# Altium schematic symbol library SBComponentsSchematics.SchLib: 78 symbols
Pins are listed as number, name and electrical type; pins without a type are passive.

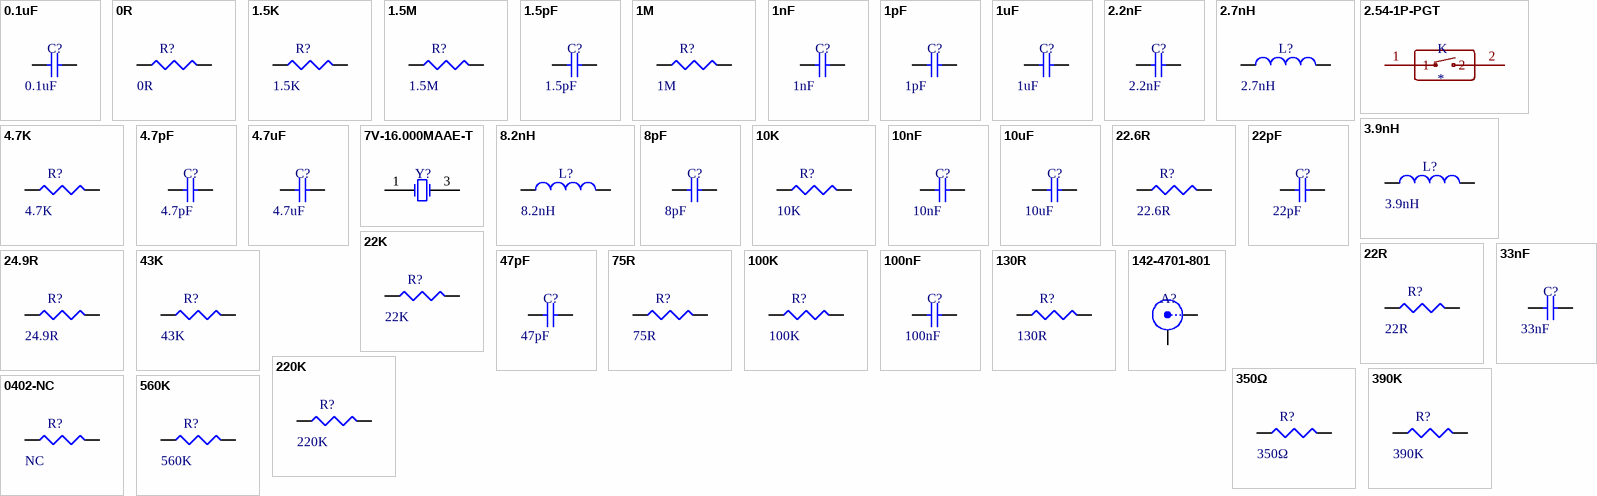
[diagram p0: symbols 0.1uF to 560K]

## 0.1uF
designator C?
footprint 0603 (Chip Body 1.6 x 0.8 mm (LxW typ))
pins: 1, 2

## 0R
designator R?
0R 0402 1/16W ±0.05R
footprint 0402 (Chip Body 1.0 x 0.5 mm (LxW typ))
footprint 0603 (Chip Body 1.6 x 0.8 mm (LxW typ))
pins: 1, 2

## 1.5K
designator R?
1.5K 0402 1/16W ±1%
footprint 0402 (Chip Body 1.0 x 0.5 mm (LxW typ))
pins: 1, 2

## 1.5M
designator R?
1.5M 0402 1/16W ±1%
footprint 0402 (Chip Body 1.0 x 0.5 mm (LxW typ))
pins: 1, 2

## 1.5pF
designator C?
1.5pF 0402 NP0/CG0 50V ±0.1pF
footprint 0402 (Chip Body 1.0 x 0.5 mm (LxW typ))
pins: 1, 2

## 1M
designator R?
1M 0402 1/16W ±1%
footprint 0402 (Chip Body 1.0 x 0.5 mm (LxW typ))
pins: 1, 2

## 1nF
designator C?
1nF 0402 NP0 50V ±5%
footprint 0402 (Chip Body 1.0 x 0.5 mm (LxW typ))
pins: 1, 2

## 1pF
designator C?
1pF 0402 NP0/CG0 50V ±0.1pF
footprint 0402 (Chip Body 1.0 x 0.5 mm (LxW typ))
pins: 1, 2

## 1uF
designator C?
1uF 0603 X5R 10V ±10%
footprint 0603 (Chip Body 1.6 x 0.8 mm (LxW typ))
pins: 1, 2

## 2.2nF
designator C?
2.2nF 0402 X7R 50V ±10%
footprint 0402 (Chip Body 1.0 x 0.5 mm (LxW typ))
pins: 1, 2

## 2.7nH
designator L?
2.7nH ±0.1nH 0402
footprint 0402 (Chip Body 1.0 x 0.5 mm (LxW typ))
pins: 1, 2

## 2.54-1P-PGT
designator K
pins: 1, 2

## 3.9nH
designator L?
3.9nH ±0.1nH 0402
footprint 0402 (Chip Body 1.0 x 0.5 mm (LxW typ))
pins: 1, 2

## 4.7K
designator R?
footprint 0402 (Chip Body 1.0 x 0.5 mm (LxW typ))
footprint 0603 (Chip Body 1.6 x 0.8 mm (LxW typ))
pins: 1, 2

## 4.7pF
designator C?
4.7pF 0402 NP0/CG0 50V ±0.25pF
footprint 0402 (Chip Body 1.0 x 0.5 mm (LxW typ))
pins: 1, 2

## 4.7uF
designator C?
4.7uF 0603 X5R 10V ±10%
footprint 0603 (Chip Body 1.6 x 0.8 mm (LxW typ))
pins: 1, 2

## 7V-16.000MAAE-T
designator Y?
TXC - 7V-16.000MAAE-T, 16MHZ, 30PPM, 12PF - CRYSTAL
footprint 3.2x2.5 CRYSTAL
pins: 1 X1, 2 GND hidden to GND, 3 X2, 4 GND hidden to GND

## 8.2nH
designator L?
8.2nH ±0.2nH 0402
footprint 0402 (Chip Body 1.0 x 0.5 mm (LxW typ))
pins: 1, 2

## 8pF
designator C?
8pF 0402 C0G/NP0 50V ±0.5pF
footprint 0402 (Chip Body 1.0 x 0.5 mm (LxW typ))
pins: 1, 2

## 10K
designator R?
10K 0402 1/16W ±1%
footprint 0402 (Chip Body 1.0 x 0.5 mm (LxW typ))
pins: 1, 2

## 10nF
designator C?
10nF 0402 X7R 25V ±5%
footprint 0402 (Chip Body 1.0 x 0.5 mm (LxW typ))
pins: 1, 2

## 10uF
designator C?
10uF 0603 X5R 6.3V ±20%
footprint 0603 (Chip Body 1.6 x 0.8 mm (LxW typ))
pins: 1, 2

## 22.6R
designator R?
22.6R 0402 1/16W ±0.05R
footprint 0402 (Chip Body 1.0 x 0.5 mm (LxW typ))
pins: 1, 2

## 22K
designator R?, comment value 22K  (hidden comment: 22K 0402 1/16W ±1%)
footprint 0402 (Chip Body 1.0 x 0.5 mm (LxW typ))
pins: 1, 2

## 22pF
designator C?
22pF 0402 NP0/CG0 50V ±5%
footprint 0402 (Chip Body 1.0 x 0.5 mm (LxW typ))
pins: 1, 2

## 22R
designator R?
22R 0402 1/16W ±1%
footprint 0402 (Chip Body 1.0 x 0.5 mm (LxW typ))
pins: 1, 2

## 24.9R
designator R?
24.9R 0402 1/16W ±0.05R
footprint 0402 (Chip Body 1.0 x 0.5 mm (LxW typ))
pins: 1, 2

## 33nF
designator C?
33nF 0402 X7R 50V ±10%
footprint 0402 (Chip Body 1.0 x 0.5 mm (LxW typ))
pins: 1, 2

## 43K
designator R?
43K 0402 1/16W ±1%
footprint 0402 (Chip Body 1.0 x 0.5 mm (LxW typ))
pins: 1, 2

## 47pF
designator C?
47pF 0402 NP0 50V ±5%
footprint 0402 (Chip Body 1.0 x 0.5 mm (LxW typ))
pins: 1, 2

## 75R
designator R?
75R 0402 1/16W ±1%
footprint 0402 (Chip Body 1.0 x 0.5 mm (LxW typ))
pins: 1, 2

## 100K
designator R?
100K 0402 1/16W ±1%
footprint 0402 (Chip Body 1.0 x 0.5 mm (LxW typ))
pins: 1, 2

## 100nF
designator C?
100nF 0402 X7R 16V ±10%
footprint 0402 (Chip Body 1.0 x 0.5 mm (LxW typ))
pins: 1, 2

## 130R
designator R?
130R 0402 1/16W ±0.05R
footprint 0402 (Chip Body 1.0 x 0.5 mm (LxW typ))
pins: 1, 2

## 142-4701-801
designator A?  (value not drawn)
JOHNSON  142-4701-801  SMA FEMELLE REVERSE POLARITY TERMINAISON
footprint 142-4701-801
pins: 1 X, 2 Y

## 220K
designator R?  value 220K
220K 0402 1/16W ±1%
footprint 0402 (Chip Body 1.0 x 0.5 mm (LxW typ))
pins: 1, 2

## 350Ω
designator R?
footprint 0402 (Chip Body 1.0 x 0.5 mm (LxW typ))
footprint 0603 (Chip Body 1.6 x 0.8 mm (LxW typ))
pins: 1, 2

## 390K
designator R?  value 390K
390K 0402 1/16W ±1%
footprint 0402 (Chip Body 1.0 x 0.5 mm (LxW typ))
pins: 1, 2

## 0402-NC
designator R?  value NC  (hidden comment: 0402-NC)
NOT CONNECTED
footprint 0402 - NOBODY (Chip Body 1.0 x 0.5 mm (LxW typ))
pins: 1, 2

## 560K
designator R?
560K 0402 1/16W ±1%
footprint 0402 (Chip Body 1.0 x 0.5 mm (LxW typ))
pins: 1, 2

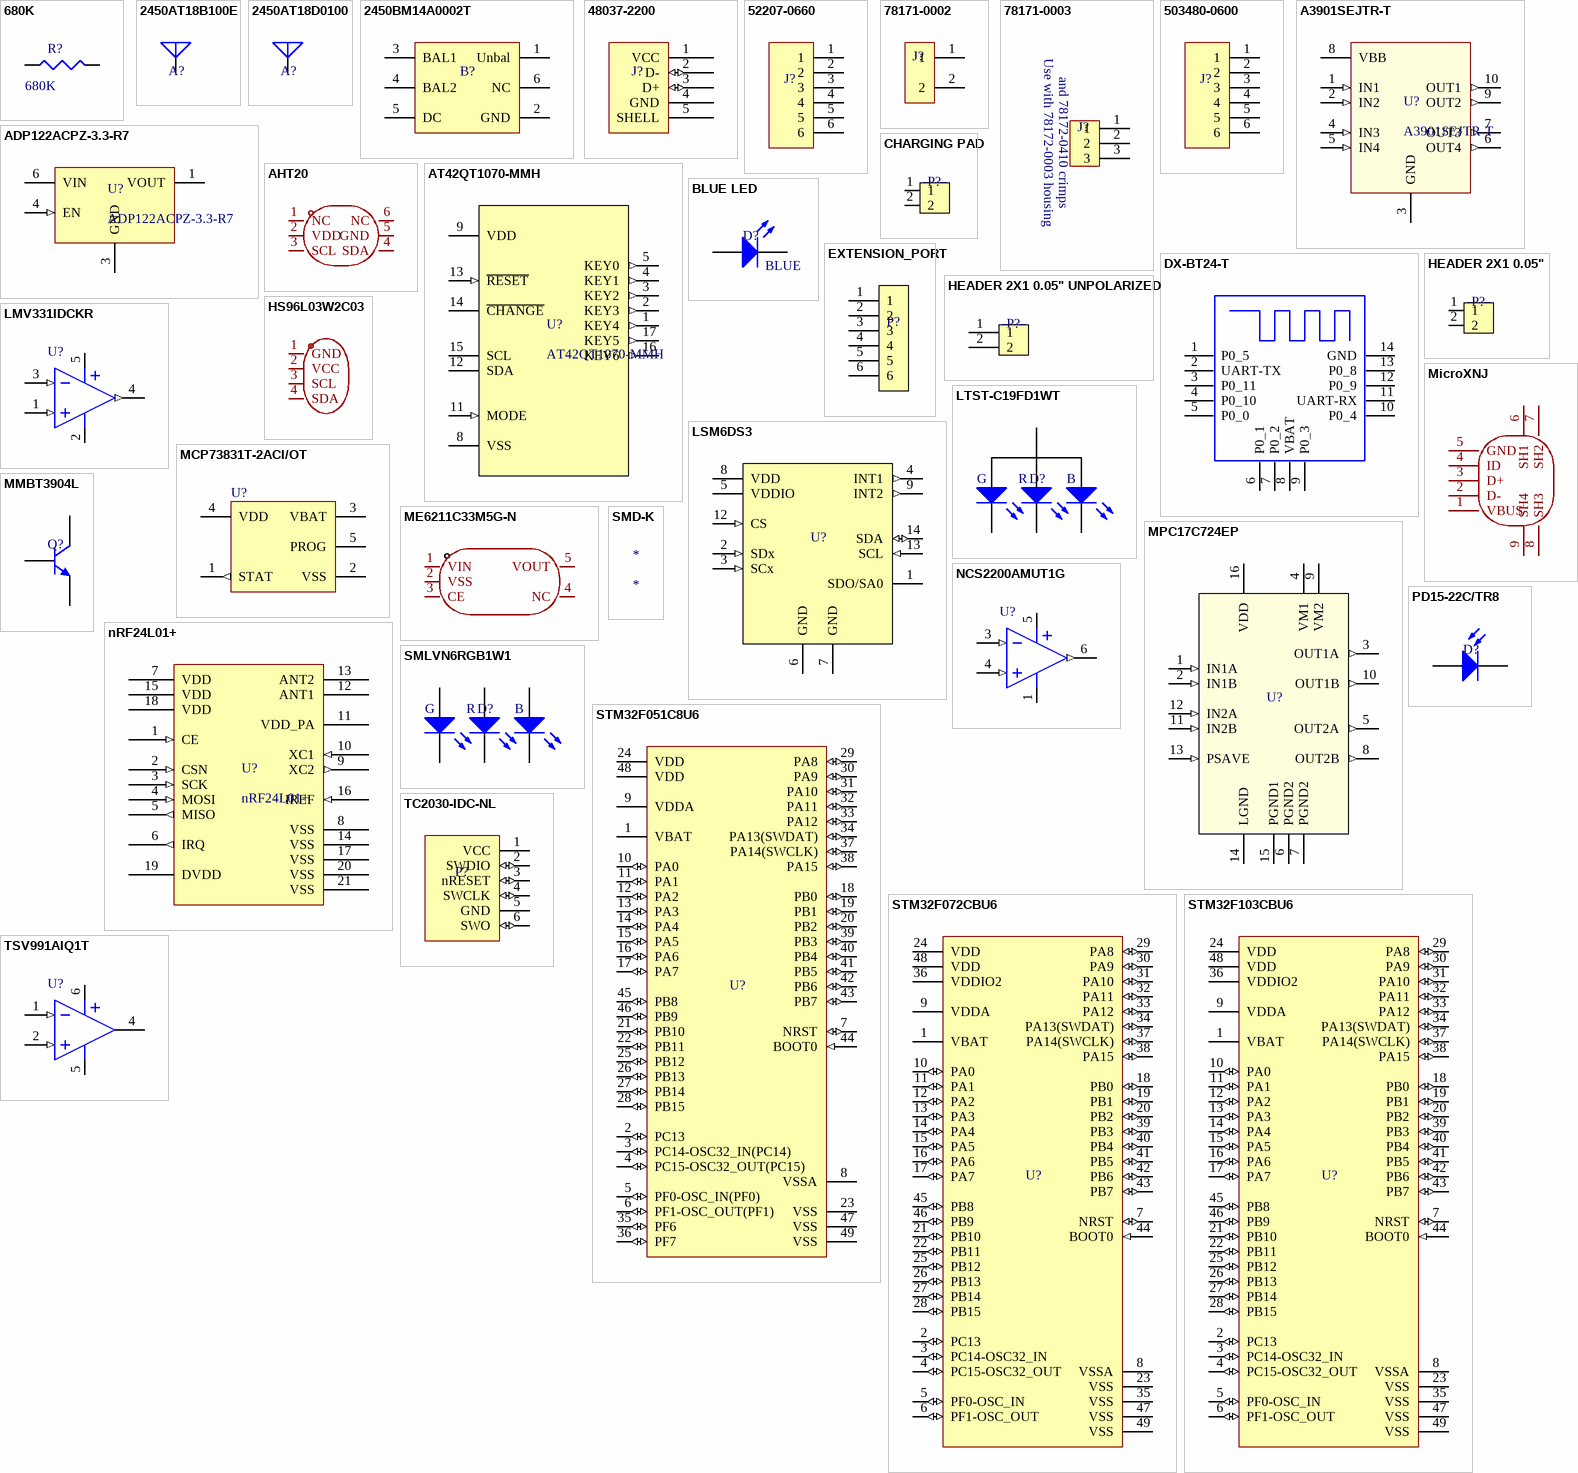
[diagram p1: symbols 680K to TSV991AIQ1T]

## 680K
designator R?  value 680K
680K 0402 1/16W ±1%
footprint 0402 (Chip Body 1.0 x 0.5 mm (LxW typ))
pins: 1, 2

## 2450AT18B100E
designator A?  (value not drawn)
JOHANSON TECHNOLOGY 2450AT18B100E  ANTENNA, CERAMIC, 2.45GHZ
footprint 2450AT18B100E (ANTENNA CHIP 2.4GHZ)
pins: 1 A

## 2450AT18D0100
designator A?  (value not drawn)
JOHANSON TECHNOLOGY 2450AT18D0100  ANTENNA, CERAMIC, 2.45GHZ
footprint 2450AT18D0100 (ANTENNA CHIP 2.4GHZ)
pins: 1 A, 2 GND hidden to GND

## 2450BM14A0002T
designator B?  (value not drawn)
Johanson Technology Impedance Matched Balun Filter Integrated Passive for nRF24L01
footprint 2450BM14A0002 (2.45 GHz Impedance Matched Balun-Filter: Optimized for Nordic's Chipset nRF24L01)
pins: 1 Unbal, 2 GND, 3 BAL1, 4 BAL2, 5 DC, 6 NC

## 48037-2200
designator J?  (value not drawn)
Molex USB 2.0 Connector Plug USB Type A
footprint 48037-2200 (Molex 48037-2200 USB Type A Receptacle)
pins: 1 VCC (power), 2 D- (io), 3 D+ (io), 4 GND (power), 5 SHELL (power)

## 52207-0660
designator J?  (value not drawn)
Easy-On™ Type FFC/FPC Connector, Right-Angle, Surface Mount, ZIF, Top Contact Style Receptacle, 6 Circuits, Gold (Au) Contact Plating, High Barrier Packaging
pins: 1, 2, 3, 4, 5, 6

## 78171-0002
designator J?  (value not drawn)
Molex Pico-EZmate™ Wire-to-Board Header, 2 contacts
footprint 78171-0002
pins: 1, 2

## 78171-0003
designator J?  (value not drawn)
Molex Pico-EZmate™ Wire-to-Board Header, 3 contacts
footprint 78171-0003
pins: 1, 2, 3

## 503480-0600
designator J?  (value not drawn)
Molex 0.50mm Pitch Easy-On™ BackFlip™ Type FPC Connector, 6 contacts
footprint 503480-0600
pins: 1, 2, 3, 4, 5, 6

## A3901SEJTR-T
designator U?
ALLEGRO MICROSYSTEMS - A3901SEJTR-T - IC, MOTOR DRIVER
footprint DFN50P300X300X75_HS-11N
pins: 1 IN1 (in), 2 IN2 (in), 3 GND (power), 4 IN3 (in), 5 IN4 (in), 6 OUT4 (out), 7 OUT3 (out), 8 VBB (power), 9 OUT2 (out), 10 OUT1 (out), 11 PAD (power) hidden to GND

## ADP122ACPZ-3.3-R7
designator U?
Analog Devices ADP122ACPZ-3.3-R7 - 5.5 V Input, 300 mA, Low Quiescent  Current, CMOS Linear Regulator
footprint LFCSP-6 2.0X2.0X0.55 (. 6-Lead Lead Frame Chip Scale Package [LFCSP_UD]  2.00 mm× 2.00 mm Body, Ultra Thin, Dual Lead  (CP-6-3))
pins: 1 VOUT (power) "Regulated Output Voltage.", 2 NC hidden to GND "No Connect. These pins are not internally bonded. They can be left floating or connected  to ground.", 3 GND (power) "Ground", 4 EN (in) "N Enable Input. Drive EN high to turn on the regulator; drive EN low to turn off the  regulator. For automatic startup, connect EN to VIN.", 5 NC hidden to GND "No Connect. These pins are not internally bonded. They can be left floating or connected  to ground.", 6 VIN (power) "Regulator Input Supply.", 7 THPAD hidden to GND "Thermal Pad"

## AHT20
designator U?  (value not drawn)
Manufacturer: 广州奥松; Symbol: AHT20_C2757850; Add into BOM: yes
footprint SENSOR-SMD_L3.0-W3.0-P1.00-BR
3D model SENSOR-SMD_L3.0-W3.0-P1.00-BL
pins: 1 NC, 2 VDD, 3 SCL, 4 SDA, 5 GND, 6 NC

## AT42QT1070-MMH
designator U?
Atmel Seven-channel QTouch® Touch Sensor IC
footprint QFN45P300X300X85_HS-21L (QFN, 20-Leads, Body 3.00x3.00mm, Pitch 0.45mm, Thermal Pad 1.55x1.55mm, IPC High Density)
pins: 1 KEY4 (out), 2 KEY3 (out), 3 KEY2 (out), 4 KEY1 (out), 5 KEY0 (out), 6 NC hidden, 7 NC hidden, 8 VSS (power), 9 VDD (power), 10 NC hidden, 11 MODE (in), 12 SDA (oc), 13 ~{RESET} (in), 14 ~{CHANGE} (oc), 15 SCL (oc), 16 KEY6 (out), 17 KEY5 (out), 18 NC hidden, 19 NC hidden, 20 NC hidden, 21 PAD (power) hidden to GND

## BLUE LED
designator D?  value BLUE
BRIGHT BLUE LED 20mA
footprint 0603 - LED (Chip Body 1.6 x 0.8 mm (LxW typ))
pins: 1 A, 2 K

## CHARGING PAD
designator P?  (value not drawn)
footprint Charging Pad
pins: 1, 2

## DX-BT24-T
designator U???  (value not drawn)
PCB DECAL: DX-BT24-S
footprint DX-BT24-T (Footprint not found)
pins: 1 P0_5, 2 UART-TX, 3 P0_11, 4 P0_10, 5 P0_0, 6 P0_1, 7 P0_2, 8 VBAT, 9 P0_3, 10 P0_4, 11 UART-RX, 12 P0_9, 13 P0_8, 14 GND

## EXTENSION_PORT
designator P?  (value not drawn)
footprint EXTENSION_PORT
pins: 1, 2, 3, 4, 5, 6

## HEADER 2X1 0.05"
designator P?  (value not drawn)
footprint HEADER 2X1 0.05" (Footprint not found)
pins: 1, 2

## HEADER 2X1 0.05" UNPOLARIZED
designator P?  (value not drawn)
footprint HEADER 2X1 0.05" - UNPOLARIZED
pins: 1, 2

## HS96L03W2C03
designator U?  (value not drawn)
Manufacturer: HS(汉昇); Add into BOM: yes; Main Control Chip: SSD1315; Interface Type: I2C; Pixel Resolution: 128x64
footprint OLED-TH_L27.8-W27.2-P2.54_C9900033791
3D model OLED-TH_L27.8-W27.2-P2.54_C9900033791
pins: 1 GND, 2 VCC, 3 SCL, 4 SDA

## LMV331IDCKR
designator U?
TI LMV331 Single General-purpose Low-voltage Comparators
footprint SC70-5
pins: 1 IN+ (in), 2 GND (power), 3 IN- (in), 4 OUT (out), 5 VCC (power)

## LSM6DS3
designator U?
STMicroelectronics iNEMO inertial module:   3D accelerometer and 3D gyroscope
footprint LGA-14 2.5x3x0.86 mm 14L (LGA, 14-Leads, Body 3.00x2.50mm, Pitch 0.50mm, IPC High Density)
pins: 1  SDO/SA0 (power), 2 SDx (in), 3 SCx (in), 4 INT1 (out), 5 VDDIO (power), 6 GND (power), 7 GND (power), 8 VDD (power), 9 INT2 (out), 10 OCS hidden, 11 NC hidden, 12 CS (in), 13 SCL (in), 14 SDA (io)

## LTST-C19FD1WT
designator D?
Lite-On Inc. LTST-C19FD1WT
footprint 2.1X1.6X0.55_4SMD
pins: 1 KB, 2 KR, 3 KG, 4 A

## MCP73831T-2ACI/OT
designator U?
Miniature Single-Cell, Fully Integrated Li-Ion, Li-Polymer Charge Management Controller, 4.2V, 5-Pin SOT-23, Industrial Temperature, Tape and Reel
footprint SOT-23-OT5_N (SOT23, 5-Leads, Body 2.9x1.6mm, Pitch 0.95mm, Lead Span 2.7mm, IPC Medium Density)
footprint SOT-23-OT5_L (SOT23, 5-Leads, Body 2.9x1.6mm, Pitch 0.95mm, Lead Span 2.7mm, IPC High Density)
footprint SOT-23-OT5_M (SOT23, 5-Leads, Body 2.9x1.6mm, Pitch 0.95mm, Lead Span 2.7mm, IPC Low Density)
pins: 1 STAT (out), 2 VSS (power), 3 VBAT (power), 4 VDD (power), 5 PROG

## ME6211C33M5G-N
designator LDO?  (value not drawn)
Manufacturer: MICRONE(南京微盟); Add into BOM: yes; Output Type: 固定; Voltage - Supply: 6V; Output Voltage: 3.3V; Output Current: 500mA; Power Supply Rejection Ratio (PSRR): 70dB@(1kHz)；62dB@(10kHz); Voltage Dropout: 260mV@(200mA); Output Configuration: 正极; Number of Outputs: 1
footprint SOT-23-5_L3.0-W1.7-P0.95-LS2.8-BL
3D model SOT-23-5_L2.9-W1.6-H1.1-LS2.8-P0.95
footprint SOT-23-OT5_L (SOT23, 5-Leads, Body 2.9x1.6mm, Pitch 0.95mm, Lead Span 2.7mm, IPC High Density)
pins: 1 VIN, 2 VSS, 3 CE, 4 NC, 5 VOUT

## MicroXNJ
designator USB?  (value not drawn)
Manufacturer: SHOU HAN(首韩); Add into BOM: yes; Connector Type: Micro-B; Gender: 母; Number of Contacts: 5P; Number of Ports: 1; Current Rating - Power (Max): 1.8A; Rated Voltage (Max): 30V; Connect-Disconnect Life: 5千次; Core Colour: 黑色
footprint MICRO-USB-SMD_MICROXNJ
3D model MICRO-USB-SMD_MICROXNJ-A
footprint MICRO_USB_B
pins: 1 VBUS, 2 D-, 3 D+, 4 ID, 5 GND, 6 SH1, 7 SH2, 8 SH3, 9 SH4

## MMBT3904L
designator Q?  (value not drawn)
On Semiconductor MMBT3904L General Purpose Transistor  NPN Silicon
footprint SOT23_L (SOT23, 3-Leads, Body 2.9x1.3mm, Pitch 0.95mm, Lead Span 2.3mm - Reverse Pinning, IPC High Density)
pins: 1 B, 2 E, 3 C

## MPC17C724EP
designator U?
Fresscale Semiconductor MPC17C724EP 0.4 A Dual H-Bridge Motor Driver IC
footprint QFN50P300X300X90_HS-17L (QFN, 16-Leads, Body 3,00x3,00mm, Pitch 0,50mm, Thermal Pad 1,70x1,70mm, IPC High Density)
pins: 1 IN1A (in) "Logic Input Control 1A", 2 IN1B (in) "Logic Input Control 2A", 3 OUT1A (out) "H-Bridge Output 1A", 4 VM1 (power) "Motor Driver Power Supply 1", 5 OUT2A (out) "H-Bridge Output 2A", 6 PGND2 "Power Ground 2", 7 PGND2 "Power Ground 2", 8 OUT2B (out) "H-Bridge Output 2B", 9 VM2 (power) "Motor Driver Power Supply 2", 10 OUT1B (out) "H-Bridge Output 1B", 11 IN2B (in) "Logic Input Control 2B", 12 IN2A (in) "Logic Input Control 2A", 13 PSAVE (in) "Input Enable Control", 14 LGND "Logic Ground", 15 PGND1 "Power Ground 1", 16 VDD (power) "Logic Circuit Power Supply"

## NCS2200AMUT1G
designator U?
Low Voltage Comparator
footprint UDFN6-1.2x1.0
pins: 1 GND (power), 3 IN- (in), 4 IN+ (in), 5 VCC (power), 6 OUT (out)

## nRF24L01+
designator U?
Nordic Semi Ultra low power 2.4GHz RF Transceiver IC
footprint QFN50P400X400X95_HS-21L (QFN, 20-Leads, Body 4,00x4,00mm, Pitch 0,50mm, Thermal Pad 2,60x2,60mm, IPC High Density)
pins: 1 CE (in) "Chip Enable Activates RX or TX mode", 2 CSN (in) "SPI Chip Select", 3 SCK (in) "SPI Clock", 4 MOSI (in) "SPI Slave Data Input", 5 MISO (out) "SPI Slave Data Output, with tri-state option", 6 IRQ (out) "Maskable interrupt pin. Active low", 7 VDD (power) "Power Supply (+1.9V - +3.6V DC)", 8 VSS (power) "Ground (0V)", 9 XC2 (out) "Crystal Pin 2", 10 XC1 (in) "Crystal Pin 1", 11 VDD_PA (power) "Power Supply Output (+1.8V) for the internal  nRF24L01+ Power Amplifier. Must be connected  to ANT1 and ANT2 as shown in Figure 32", 12 ANT1 "Antenna interface 1", 13 ANT2 "Antenna interface 1", 14 VSS (power) "Ground (0V)", 15 VDD (power) "Power Supply (+1.9V - +3.6V DC)", 16 IREF (in) "Reference current. Connect a 22kΩ resistor to  ground. See Figure 32.", 17 VSS (power) "Ground (0V)", 18 VDD (power) "Power Supply (+1.9V - +3.6V DC)", 19 DVDD (power) "Internal digital supply output for de-coupling purposes.  See Figure 32.", 20 VSS (power) "Ground (0V)", 21 VSS (power) "Ground (0V) - Thermal Pad"

## PD15-22C/TR8
designator D?  (value not drawn)
Everlight PD15-22C/TR8 Silicon PIN Photodiode
footprint PD15-22C/TR8 (Silicon PIN Photodiode)
pins: 1 A, 2 K

## SMD-K
designator *

## SMLVN6RGB1W1
designator D?
ROHM SMLVN6RGB1W1 LED Tri-Color Blue/Green/Red Chip LED 6-Pin 1411 T/RLED Tri-Color Blue/Green/Red Chip LED 6-Pin 1411
footprint 3.5x2.8 mm 6-SMD (3.5 x 2.8 mm 6-SMD Flat Leads)
pins: 1 AB, 2 AR, 3 AG, 4 KG, 5 KR, 6 KB

## STM32F051C8U6
designator U?
STMICROELECTRONICS  STM32F051C8U6  MCU 32BIT CORTEX-M0 48MHZ UFQFPN-48
footprint QFN50P700X700X60_HS-49L (QFN, 48-Leads, Body 7,00x7,00mm, Pitch 0,50mm, Thermal Pad 5,60x5,60mm, IPC High Density)
pins: 1 VBAT (power) "Backup power supply", 2 PC13 (io) "PC13/RTC_TAMP1,RTC_TS,RTC_OUT,WKUP2", 3 PC14-OSC32_IN(PC14) (io) "PC14-OSC32_IN(PC14)/OSC32_IN", 4 PC15-OSC32_OUT(PC15) (io) "PC15-OSC32_OUT(PC15)/OSC32_OUT", 5 PF0-OSC_IN(PF0) (io) "PF0-OSC_IN(PF0)/OSC_IN", 6 PF1-OSC_OUT(PF1) (io) "PF1-OSC_OUT(PF1)/OSC_OUT", 7 NRST (io) "Device  reset  input  /  internal  reset  output  (active  low)", 8 VSSA (power) "Analog ground", 9 VDDA (power) "Analog power supply", 10 PA0 (io) "PA0/USART2_CTS,TIM2_CH1_ETR,COMP1_OUT,TSC_G1_IO1/ADC_IN0,COMP1_INM6,RTC_TAMP2,WKUP1", 11 PA1 (io) "PA1/USART2_RTS,TIM2_CH2,TSC_G1_IO2,EVENTOUT/ADC_IN1,COMP1_INP", 12 PA2 (io) "PA2/USART2_TX,TIM2_CH3,TIM15_CH1,COMP2_OUT,TSC_G1_IO3/ADC_IN2,COMP2_INM6", 13 PA3 (io) "PA3/USART2_RX,TIM2_CH4,TIM15_CH2,TSC_G1_IO4/ADC_IN3,COMP2_INP", 14 PA4 (io) "PA4/SPI1_NSS/I2S1_WS,USART2_CK,TIM14_CH1,TSC_G2_IO1/ADC_IN4,COMP1_INM4,COMP2_INM4,DAC1_OUT", 15 PA5 (io) "PA5/SPI1_SCK/I2S1_CK,CEC,TIM2_CH1_ETR,TSC_G2_IO2/ADC_IN5,COMP1_INM5,COMP2_INM5", 16 PA6 (io) "PA6/SPI1_MISO/I2S1_MCK,TIM3_CH1,TIM1_BKIN,TIM16_CH1,COMP1_OUT,TSC_G2_IO3,EVENTOUT/ADC_IN6", 17 PA7 (io) "PA7/SPI1_MOSI/I2S1_SD,TIM3_CH2,TIM14_CH1,TIM1_CH1N,TIM17_CH1,COMP2_OUT,TSC_G2_IO4,EVENTOUT/ADC_IN7", 18 PB0 (io) "PB0/TIM3_CH3,TIM1_CH2N,TSC_G3_IO2,EVENTOUT/ADC_IN8", 19 PB1 (io) "PB1/TIM3_CH4,TIM14_CH1,TIM1_CH3N,TSC_G3_IO3/ADC_IN9", 20 PB2 (io) "PB2/TSC_G3_IO4", 21 PB10 (io) "PB10/I2C2_SCL,CEC,TIM2_CH3,TSC_SYNC", 22 PB11 (io) "PB11/I2C2_SDA,TIM2_CH4,TSC_G6_IO1,EVENTOUT", 23 VSS (power) "Ground", 24 VDD (power) "Digital power supply", 25 PB12 (io) "PB12/SPI2_NSS,TIM1_BKIN,TSC_G6_IO2,EVENTOUT", 26 PB13 (io) "PB13/SPI2_SCK,TIM1_CH1N,TSC_G6_IO3", 27 PB14 (io) "PB14/SPI2_MISO,TIM1_CH2N,TIM15_CH1,TSC_G6_IO4", 28 PB15 (io) "PB15/SPI2_MOSI,TIM1_CH3N,TIM15_CH1N,TIM15_CH2/RTC_REFIN", 29 PA8 (io) "PA8/USART1_CK,TIM1_CH1,EVENTOUT,MCO", 30 PA9 (io) "PA9/USART1_TX,TIM1_CH2,TIM15_BKIN,TSC_G4_IO1", 31 PA10 (io) "PA10/USART1_RX,TIM1_CH3,TIM17_BKIN,TSC_G4_IO2", 32 PA11 (io) "PA11/USART1_CTS,TIM1_CH4,COMP1_OUT,TSC_G4_IO3,EVENTOUT", 33 PA12 (io) "PA12/USART1_RTS,TIM1_ETR,COMP2_OUT,TSC_G4_IO4,EVENTOUT", 34 PA13(SWDAT) (io) "PA13(SWDAT)/IR_OUT,SWDAT", 35 PF6 (io) "PF6/I2C2_SCL", 36 PF7 (io) "PF7/I2C2_SDA", 37 PA14(SWCLK) (io) "PA14(SWCLK)/USART2_TX,SWCLK", 38 PA15 (io) "PA15/SPI1_NSS/I2S1_WS,USART2_RX,TIM2_CH1_ETR,EVENTOUT", 39 PB3 (io) "PB3/SPI1_SCK/I2S1_CK,TIM2_CH2,TSC_G5_IO1,EVENTOUT", 40 PB4 (io) "PB4/SPI1_MISO/I2S1_MCK,TIM3_CH1,TSC_G5_IO2,EVENTOUT", 41 PB5 (io) "PB5/SPI1_MOSI,I2S1_SD,I2C1_SMBA,TIM16_BKIN,TIM3_CH2", 42 PB6 (io) "PB6/I2C1_SCL,USART1_TX,TIM16_CH1N,TSC_G5_IO3", 43 PB7 (io) "PB7/I2C1_SDA,USART1_RX,TIM17_CH1N,TSC_G5_IO4", 44 BOOT0 (in) "Boot memory selection", 45 PB8 (io) "PB8/I2C1_SCL,CEC,TIM16_CH1,TSC_SYNC", 46 PB9 (io) "PB9/I2C1_SDA,IR_OUT,TIM17_CH1,EVENTOUT", 47 VSS (power) "Ground", 48 VDD (power) "Digital power supply", 49 VSS (power) "Grounded Thermal Pad"

## STM32F072CBU6
designator U?
STMICROELECTRONICS  STM32F072CBU6  MCU 32 BITS CORTEX-M0 48MHZ UFQFPN-48
footprint QFN50P700X700X60_HS-49L (QFN, 48-Leads, Body 7,00x7,00mm, Pitch 0,50mm, Thermal Pad 5,60x5,60mm, IPC High Density)
pins: 1 VBAT (power) "Backup power supply", 2 PC13 (io) "PC13/RTC_TAMP1,RTC_TS,RTC_OUT,WKUP2", 3 PC14-OSC32_IN (io) "PC14-OSC32_IN(PC14)/OSC32_IN", 4 PC15-OSC32_OUT (io) "PC15-OSC32_OUT(PC15)/OSC32_OUT", 5 PF0-OSC_IN (io) "PF0-OSC_IN(PF0)/OSC_IN", 6 PF1-OSC_OUT (io) "PF1-OSC_OUT(PF1)/OSC_OUT", 7 NRST (io) "Device  reset  input  /  internal  reset  output  (active  low)", 8 VSSA (power) "Analog ground", 9 VDDA (power) "Analog power supply", 10 PA0 (io) "PA0/USART2_CTS,TIM2_CH1_ETR,COMP1_OUT,TSC_G1_IO1/ADC_IN0,COMP1_INM6,RTC_TAMP2,WKUP1", 11 PA1 (io) "PA1/USART2_RTS,TIM2_CH2,TSC_G1_IO2,EVENTOUT/ADC_IN1,COMP1_INP", 12 PA2 (io) "PA2/USART2_TX,TIM2_CH3,TIM15_CH1,COMP2_OUT,TSC_G1_IO3/ADC_IN2,COMP2_INM6", 13 PA3 (io) "PA3/USART2_RX,TIM2_CH4,TIM15_CH2,TSC_G1_IO4/ADC_IN3,COMP2_INP", 14 PA4 (io) "PA4/SPI1_NSS/I2S1_WS,USART2_CK,TIM14_CH1,TSC_G2_IO1/ADC_IN4,COMP1_INM4,COMP2_INM4,DAC1_OUT", 15 PA5 (io) "PA5/SPI1_SCK/I2S1_CK,CEC,TIM2_CH1_ETR,TSC_G2_IO2/ADC_IN5,COMP1_INM5,COMP2_INM5", 16 PA6 (io) "PA6/SPI1_MISO/I2S1_MCK,TIM3_CH1,TIM1_BKIN,TIM16_CH1,COMP1_OUT,TSC_G2_IO3,EVENTOUT/ADC_IN6", 17 PA7 (io) "PA7/SPI1_MOSI/I2S1_SD,TIM3_CH2,TIM14_CH1,TIM1_CH1N,TIM17_CH1,COMP2_OUT,TSC_G2_IO4,EVENTOUT/ADC_IN7", 18 PB0 (io) "PB0/TIM3_CH3,TIM1_CH2N,TSC_G3_IO2,EVENTOUT/ADC_IN8", 19 PB1 (io) "PB1/TIM3_CH4,TIM14_CH1,TIM1_CH3N,TSC_G3_IO3/ADC_IN9", 20 PB2 (io) "PB2/TSC_G3_IO4", 21 PB10 (io) "PB10/I2C2_SCL,CEC,TIM2_CH3,TSC_SYNC", 22 PB11 (io) "PB11/I2C2_SDA,TIM2_CH4,TSC_G6_IO1,EVENTOUT", 23 VSS (power) "Ground", 24 VDD (power) "Digital power supply", 25 PB12 (io) "PB12/SPI2_NSS,TIM1_BKIN,TSC_G6_IO2,EVENTOUT", 26 PB13 (io) "PB13/SPI2_SCK,TIM1_CH1N,TSC_G6_IO3", 27 PB14 (io) "PB14/SPI2_MISO,TIM1_CH2N,TIM15_CH1,TSC_G6_IO4", 28 PB15 (io) "PB15/SPI2_MOSI,TIM1_CH3N,TIM15_CH1N,TIM15_CH2/RTC_REFIN", 29 PA8 (io) "PA8/USART1_CK,TIM1_CH1,EVENTOUT,MCO", 30 PA9 (io) "PA9/USART1_TX,TIM1_CH2,TIM15_BKIN,TSC_G4_IO1", 31 PA10 (io) "PA10/USART1_RX,TIM1_CH3,TIM17_BKIN,TSC_G4_IO2", 32 PA11 (io) "PA11/USART1_CTS,TIM1_CH4,COMP1_OUT,TSC_G4_IO3,EVENTOUT", 33 PA12 (io) "PA12/USART1_RTS,TIM1_ETR,COMP2_OUT,TSC_G4_IO4,EVENTOUT", 34 PA13(SWDAT) (io) "PA13(SWDAT)/IR_OUT,SWDAT", 35 VSS (power) "Ground", 36 VDDIO2 (power) "Digital power supply", 37 PA14(SWCLK) (io) "PA14(SWCLK)/USART2_TX,SWCLK", 38 PA15 (io) "PA15/SPI1_NSS/I2S1_WS,USART2_RX,TIM2_CH1_ETR,EVENTOUT", 39 PB3 (io) "PB3/SPI1_SCK/I2S1_CK,TIM2_CH2,TSC_G5_IO1,EVENTOUT", 40 PB4 (io) "PB4/SPI1_MISO/I2S1_MCK,TIM3_CH1,TSC_G5_IO2,EVENTOUT", 41 PB5 (io) "PB5/SPI1_MOSI,I2S1_SD,I2C1_SMBA,TIM16_BKIN,TIM3_CH2", 42 PB6 (io) "PB6/I2C1_SCL,USART1_TX,TIM16_CH1N,TSC_G5_IO3", 43 PB7 (io) "PB7/I2C1_SDA,USART1_RX,TIM17_CH1N,TSC_G5_IO4", 44 BOOT0 (in) "Boot memory selection", 45 PB8 (io) "PB8/I2C1_SCL,CEC,TIM16_CH1,TSC_SYNC", 46 PB9 (io) "PB9/I2C1_SDA,IR_OUT,TIM17_CH1,EVENTOUT", 47 VSS (power) "Ground", 48 VDD (power) "Digital power supply", 49 VSS (power) "Ground"

## STM32F103CBU6
designator U?
STMICROELECTRONICS  STM32F103CBU6 ARM Cortex-M3, 72 MHz, 128 KB, 20 KB, 48, VFQFPN
footprint QFN50P700X700X60_HS-49L (QFN, 48-Leads, Body 7,00x7,00mm, Pitch 0,50mm, Thermal Pad 5,60x5,60mm, IPC High Density)
pins: 1 VBAT (power) "Backup power supply", 2 PC13 (io) "PC13/RTC_TAMP1,RTC_TS,RTC_OUT,WKUP2", 3 PC14-OSC32_IN (io) "PC14-OSC32_IN(PC14)/OSC32_IN", 4 PC15-OSC32_OUT (io) "PC15-OSC32_OUT(PC15)/OSC32_OUT", 5 PF0-OSC_IN (io) "PF0-OSC_IN(PF0)/OSC_IN", 6 PF1-OSC_OUT (io) "PF1-OSC_OUT(PF1)/OSC_OUT", 7 NRST (io) "Device  reset  input  /  internal  reset  output  (active  low)", 8 VSSA (power) "Analog ground", 9 VDDA (power) "Analog power supply", 10 PA0 (io) "PA0/USART2_CTS,TIM2_CH1_ETR,COMP1_OUT,TSC_G1_IO1/ADC_IN0,COMP1_INM6,RTC_TAMP2,WKUP1", 11 PA1 (io) "PA1/USART2_RTS,TIM2_CH2,TSC_G1_IO2,EVENTOUT/ADC_IN1,COMP1_INP", 12 PA2 (io) "PA2/USART2_TX,TIM2_CH3,TIM15_CH1,COMP2_OUT,TSC_G1_IO3/ADC_IN2,COMP2_INM6", 13 PA3 (io) "PA3/USART2_RX,TIM2_CH4,TIM15_CH2,TSC_G1_IO4/ADC_IN3,COMP2_INP", 14 PA4 (io) "PA4/SPI1_NSS/I2S1_WS,USART2_CK,TIM14_CH1,TSC_G2_IO1/ADC_IN4,COMP1_INM4,COMP2_INM4,DAC1_OUT", 15 PA5 (io) "PA5/SPI1_SCK/I2S1_CK,CEC,TIM2_CH1_ETR,TSC_G2_IO2/ADC_IN5,COMP1_INM5,COMP2_INM5", 16 PA6 (io) "PA6/SPI1_MISO/I2S1_MCK,TIM3_CH1,TIM1_BKIN,TIM16_CH1,COMP1_OUT,TSC_G2_IO3,EVENTOUT/ADC_IN6", 17 PA7 (io) "PA7/SPI1_MOSI/I2S1_SD,TIM3_CH2,TIM14_CH1,TIM1_CH1N,TIM17_CH1,COMP2_OUT,TSC_G2_IO4,EVENTOUT/ADC_IN7", 18 PB0 (io) "PB0/TIM3_CH3,TIM1_CH2N,TSC_G3_IO2,EVENTOUT/ADC_IN8", 19 PB1 (io) "PB1/TIM3_CH4,TIM14_CH1,TIM1_CH3N,TSC_G3_IO3/ADC_IN9", 20 PB2 (io) "PB2/TSC_G3_IO4", 21 PB10 (io) "PB10/I2C2_SCL,CEC,TIM2_CH3,TSC_SYNC", 22 PB11 (io) "PB11/I2C2_SDA,TIM2_CH4,TSC_G6_IO1,EVENTOUT", 23 VSS (power) "Ground", 24 VDD (power) "Digital power supply", 25 PB12 (io) "PB12/SPI2_NSS,TIM1_BKIN,TSC_G6_IO2,EVENTOUT", 26 PB13 (io) "PB13/SPI2_SCK,TIM1_CH1N,TSC_G6_IO3", 27 PB14 (io) "PB14/SPI2_MISO,TIM1_CH2N,TIM15_CH1,TSC_G6_IO4", 28 PB15 (io) "PB15/SPI2_MOSI,TIM1_CH3N,TIM15_CH1N,TIM15_CH2/RTC_REFIN", 29 PA8 (io) "PA8/USART1_CK,TIM1_CH1,EVENTOUT,MCO", 30 PA9 (io) "PA9/USART1_TX,TIM1_CH2,TIM15_BKIN,TSC_G4_IO1", 31 PA10 (io) "PA10/USART1_RX,TIM1_CH3,TIM17_BKIN,TSC_G4_IO2", 32 PA11 (io) "PA11/USART1_CTS,TIM1_CH4,COMP1_OUT,TSC_G4_IO3,EVENTOUT", 33 PA12 (io) "PA12/USART1_RTS,TIM1_ETR,COMP2_OUT,TSC_G4_IO4,EVENTOUT", 34 PA13(SWDAT) (io) "PA13(SWDAT)/IR_OUT,SWDAT", 35 VSS (power) "Ground", 36 VDDIO2 (power) "Digital power supply", 37 PA14(SWCLK) (io) "PA14(SWCLK)/USART2_TX,SWCLK", 38 PA15 (io) "PA15/SPI1_NSS/I2S1_WS,USART2_RX,TIM2_CH1_ETR,EVENTOUT", 39 PB3 (io) "PB3/SPI1_SCK/I2S1_CK,TIM2_CH2,TSC_G5_IO1,EVENTOUT", 40 PB4 (io) "PB4/SPI1_MISO/I2S1_MCK,TIM3_CH1,TSC_G5_IO2,EVENTOUT", 41 PB5 (io) "PB5/SPI1_MOSI,I2S1_SD,I2C1_SMBA,TIM16_BKIN,TIM3_CH2", 42 PB6 (io) "PB6/I2C1_SCL,USART1_TX,TIM16_CH1N,TSC_G5_IO3", 43 PB7 (io) "PB7/I2C1_SDA,USART1_RX,TIM17_CH1N,TSC_G5_IO4", 44 BOOT0 (in) "Boot memory selection", 45 PB8 (io) "PB8/I2C1_SCL,CEC,TIM16_CH1,TSC_SYNC", 46 PB9 (io) "PB9/I2C1_SDA,IR_OUT,TIM17_CH1,EVENTOUT", 47 VSS (power) "Ground", 48 VDD (power) "Digital power supply", 49 VSS (power) "Ground"

## TC2030-IDC-NL
designator P?  (value not drawn)
TagConnect TC2030-IDC-NL SWD Programming Connector
footprint TC2030-IDC-NL (TagConnector TC2030-IDC-NL)
pins: 1 VCC (power), 2 SWDIO (io), 3 nRESET (io), 4 SWCLK (io), 5 GND (power), 6 SWO (io)

## TSV991AIQ1T
designator U?
ST TSV991AIQ1T Rail-to-rail input/output 20 MHz GBP opamp
footprint DFN6-1.3x1.6x0.55
pins: 1 IN- (in), 2 IN+ (in), 4 OUT (oc), 5 GND (power), 6 VCC (power)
